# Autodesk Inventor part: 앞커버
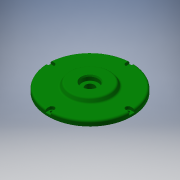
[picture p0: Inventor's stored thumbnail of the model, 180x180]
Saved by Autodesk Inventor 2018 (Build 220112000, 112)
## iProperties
Created: 2016-11
Part Number: 앞커버
Material: 알루미늄 6061
Document SubType Name: Modeling
Designer: mduedu
Density: 2.71 g/cm^3
Mass: 394.831 g
Surface Area: 366.671 cm^2
Volume: 145.694 cm^3
Appearance: 진녹색
Author: mduedu
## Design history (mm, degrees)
sketch "스케치1"
  geometry: L1 (22, -12.5)-(22, -30); L2 (22, -30)-(16, -33.464); L3 (16, -33.464)-(16, -65); L4 (16, -65)-(8, -65); L5 (8, -65)-(8, -53); L6 (8, -53)-(0, -53); L7 (0, -53)-(0, -14); L8 (0, 0)-(22, 0); L9 (8, -14)-(8, -7); L10 (8, -7)-(14.5, -7); L11 (14.5, -7)-(14.5, -12.5); L12 (0, -14)-(8, -14); L13 (14.5, -12.5)-(22, -12.5)
  constraints: 26 end point, 8 parallel, 3 perpendicular, 2 horizontal, 2 vertical alignment, 1 collinear
  dimensions: "d0" = 8 distance of L5.end L6.end; "d2" = 8 distance of L3.end L4.end; "d3" = 6 distance between parallel lines of L1 L3; "d4" = 120 deg angle of L3 L2; "d5" = 7.5 distance of L11.end L1.start; "d6" = 60 diameter of L1.end L8; "d7" = 14 diameter of L10 L8; "d8" = 28 diameter of L12 L8; "d9" = 25 diameter of L13 L8; "d10" = 106 diameter of L6 L8; "d11" = 130 diameter of L4 L8
revolve "회전1" sketch "스케치1" stored, may be unused: angle "d12" = 90 deg
fillet "모깎기1" dims "d13" = 0.3
fillet "모깎기2" dims "d14" = 3
chamfer "모따기1" distance "d15" = 1; stored, may be unused: second distance "d16" = 2, angle "d17" = 45 deg
fillet "모깎기3" dims "d18" = 0.3
chamfer "모따기2" distance "d36" = 2; stored, may be unused: second distance "d37" = 2, angle "d38" = 30 deg
sketch "스케치3"
  geometry: C1 r 65 at (0, 0) reference; A1 r 59 centre (0, 0) between (0, 59) and (59, 0); 2 further points
  constraints: 4 point on circle, 2 horizontal alignment, 2 vertical alignment, 1 centre point, 1 coincident
  dimensions: "d33" = 118 diameter of A1
sketch "스케치4"
  geometry: 4 further points
  constraints: 4 other
hole "구멍2" sketch "스케치4" at (0, 59), (-59, 0), (59, 0), (0, -59) diameter "d39" = 4.5; stored, may be unused: countersink angle "d43" = 90 deg, drill point angle "d45" = 0 deg; dims "d40" = 6, "d41" = 8, "d42" = 4.6, "d44" = 8
sketch "스케치6"
  geometry: L1 (-4, 5.877)-(-4, 0); L2 (4, 5.877)-(4, 0); A1 r 4 centre (0, 0) between (-2.712, 2.941) and (2.712, 2.941) reference; A2 r 65 centre (0, -59) between (-4, 5.877) and (4, 5.877) reference; 1 further point
  constraints: 4 end point, 4 point on circle, 2 tangent, 2 vertical
extrude "돌출2" cut sketch "스케치6" stored distance "d51" = 10; taper "d52" = 0 deg
sketch "스케치5"
  geometry: C1 r 22 at (0, 0); C2 r 45 at (0, 0); 1 further point
  constraints: 2 centre point, 2 coincident
  dimensions: "d46" = 44 diameter of C1; "d47" = 90 diameter of C2
extrude "돌출1" cut sketch "스케치5" distance "d48" = 8; taper "d49" = 0 deg
fillet "모깎기4" dims "d50" = 3
node "솔리드1"
pattern_circular "원형 패턴1" dims angle "d54" = 360 deg
